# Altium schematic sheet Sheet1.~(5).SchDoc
size B; SheetNumber: 1; SheetTotal: 1
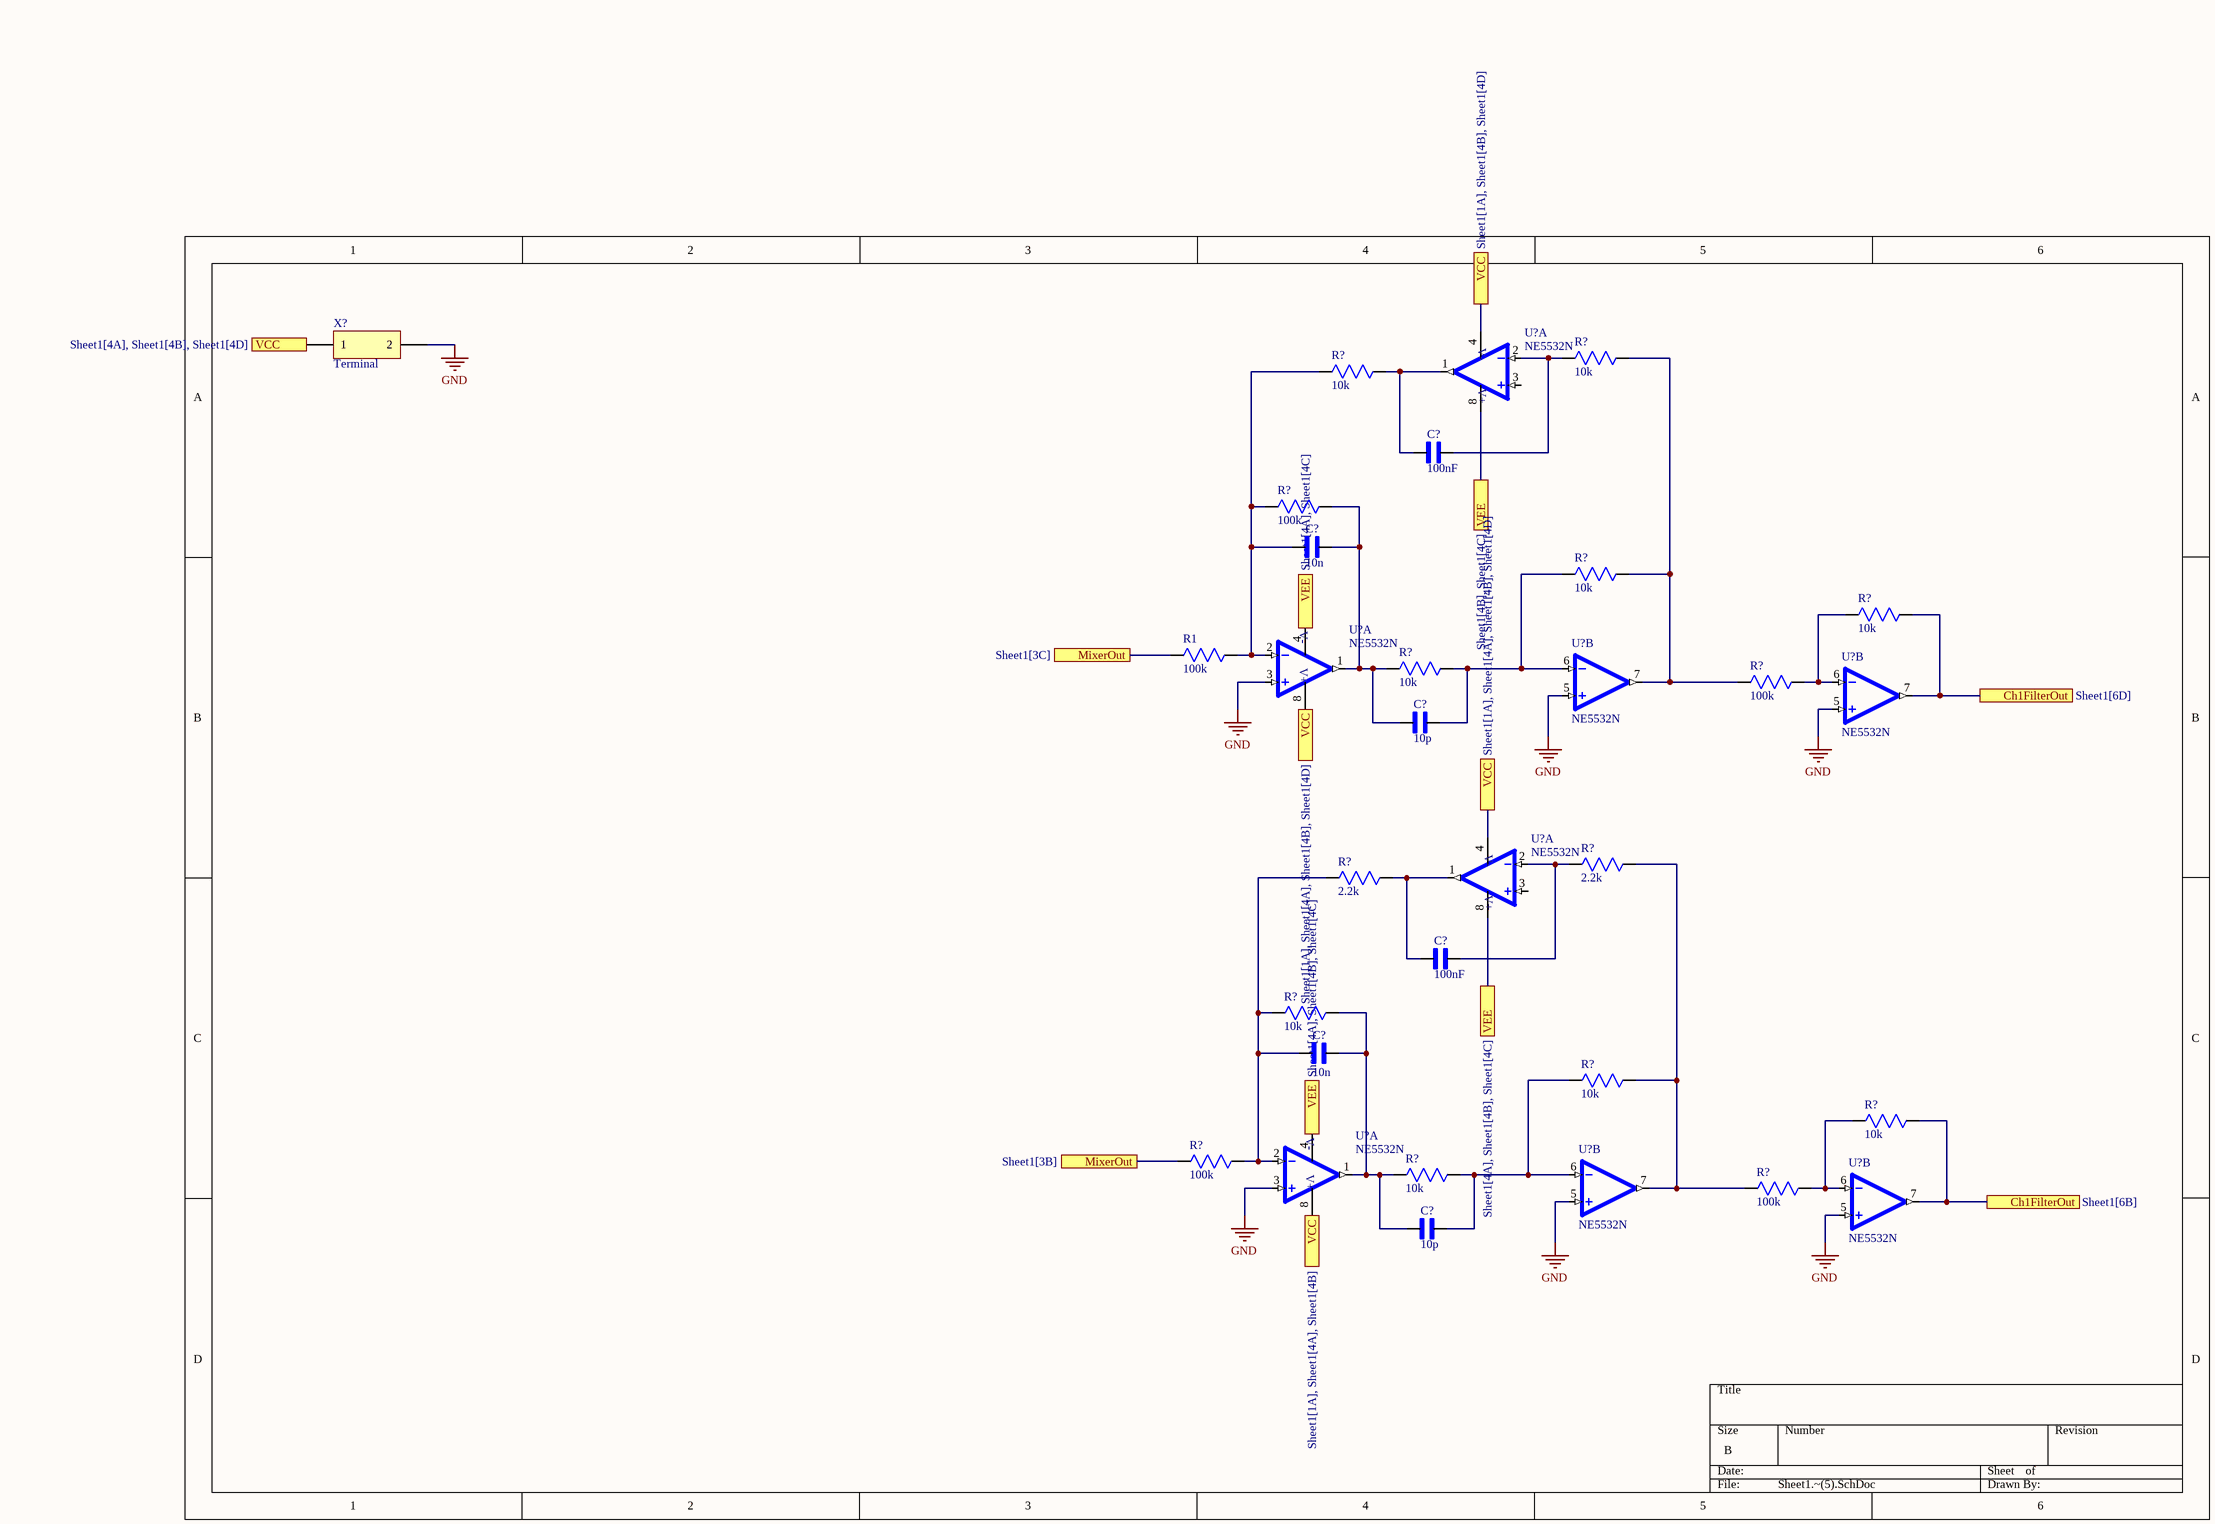
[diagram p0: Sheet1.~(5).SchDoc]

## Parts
(Parts that share a designator on the sheet are numbered #1, #2 ... from top to bottom, then left to right.)
C?#1  100nF  [CAPC2012X95N]
C?#2  10n  [CAPC2012X95N]
C?#3  10p  [CAPC2012X95N]
C?#4  100nF  [CAPC2012X95N]
C?#5  10n  [CAPC2012X95N]
C?#6  10p  [CAPC2012X95N]
R1  100k  [RC0805N_YAG-M]
R?#1  10k  [RC0805N_YAG-M]
R?#2  10k  [RC0805N_YAG-M]
R?#3  100k  [RC0805N_YAG-M]
R?#4  10k  [RC0805N_YAG-M]
R?#5  10k  [RC0805N_YAG-M]
R?#6  10k  [RC0805N_YAG-M]
R?#7  100k  [RC0805N_YAG-M]
R?#8  2.2k  [RC0805N_YAG-M]
R?#9  2.2k  [RC0805N_YAG-M]
R?#10  10k  [RC0805N_YAG-M]
R?#11  10k  [RC0805N_YAG-M]
R?#12  10k  [RC0805N_YAG-M]
R?#13  100k  [RC0805N_YAG-M]
R?#14  10k  [RC0805N_YAG-M]
R?#15  100k  [RC0805N_YAG-M]
U?#1  NE5532N  [DIP766W45P254L1016H533Q8]  (part A of 2)
U?#2  NE5532N  [DIP766W45P254L1016H533Q8]  (part A of 2)
U?#3  NE5532N  [DIP766W45P254L1016H533Q8]  (part B of 2)
U?#4  NE5532N  [DIP766W45P254L1016H533Q8]  (part B of 2)
U?#5  NE5532N  [DIP766W45P254L1016H533Q8]  (part A of 2)
U?#6  NE5532N  [DIP766W45P254L1016H533Q8]  (part A of 2)
U?#7  NE5532N  [DIP766W45P254L1016H533Q8]  (part B of 2)
U?#8  NE5532N  [DIP766W45P254L1016H533Q8]  (part B of 2)
X?  Terminal  [CON_TERMINAL_2POL]

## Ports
Ch1FilterOut (see Sheet1[6B]), Ch1FilterOut (see Sheet1[6D]), MixerOut (see Sheet1[3B]), MixerOut (see Sheet1[3C]), VCC (see Sheet1[1A], Sheet1[4A], Sheet1[4B]), VCC (see Sheet1[1A], Sheet1[4A], Sheet1[4B], Sheet1[4D]), VCC (see Sheet1[1A], Sheet1[4B], Sheet1[4D]), VCC (see Sheet1[4A], Sheet1[4B], Sheet1[4D]), VEE (see Sheet1[4A], Sheet1[4B], Sheet1[4C]), VEE (see Sheet1[4A], Sheet1[4C]), VEE (see Sheet1[4B], Sheet1[4C])

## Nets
GND: U?#2.3(+INA) U?#3.5(+INB) U?#4.5(+INB) U?#6.3(+INA) U?#7.5(+INB) U?#8.5(+INB) X?.2
Ch1FilterOut: R?#5.1 R?#12.1 U?#4.7(OUTB) U?#8.7(OUTB) ; port Ch1FilterOut
MixerOut: R1.2 R?#13.2 ; port MixerOut
VCC: U?#1.4(V-) U?#2.8(V+) U?#5.4(V-) U?#6.8(V+) X?.1 ; port VCC
VEE: U?#1.8(V+) U?#2.4(V-) U?#5.8(V+) U?#6.4(V-) ; port VEE
NetC?#1_1: C?#1.1 R?#2.1 U?#1.1(OUTA)
NetC?#1_2: C?#1.2 R?#1.2 U?#1.2(-INA)
NetC?#2_1: C?#2.1 R1.1 R?#2.2 R?#3.2 U?#2.2(-INA)
NetC?#2_2: C?#2.2 C?#3.1 R?#3.1 R?#6.2 U?#2.1(OUTA)
NetC?#3_2: C?#3.2 R?#4.2 R?#6.1 U?#3.6(-INB)
NetC?#4_1: C?#4.1 R?#9.1 U?#5.1(OUTA)
NetC?#4_2: C?#4.2 R?#8.2 U?#5.2(-INA)
NetC?#5_1: C?#5.1 R?#9.2 R?#10.2 R?#13.1 U?#6.2(-INA)
NetC?#5_2: C?#5.2 C?#6.1 R?#10.1 R?#14.2 U?#6.1(OUTA)
NetC?#6_2: C?#6.2 R?#11.2 R?#14.1 U?#7.6(-INB)
NetR?#1_1: R?#1.1 R?#4.1 R?#7.2 U?#3.7(OUTB)
NetR?#5_2: R?#5.2 R?#7.1 U?#4.6(-INB)
NetR?#8_1: R?#8.1 R?#11.1 R?#15.2 U?#7.7(OUTB)
NetR?#12_2: R?#12.2 R?#15.1 U?#8.6(-INB)

Not connected (* = marked no-connect by the designer): U?#1 3(+INA); U?#5 3(+INA)

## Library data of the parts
C?#1 C?#4 = CAP_0805_GENERIC: 0.1 ÂµF Â±10% 50V Ceramic Capacitor X7R 0805 (2012 Metric); MF: Samsung Electro-Mechanics; MP: CL21B104KBCNNNC
C?#2 C?#3 C?#5 C?#6 = CAP_0805_GENERIC: 0.1 ÂµF Â±10% 50V Ceramic Capacitor X7R 0805 (2012 Metric); Value: 100nF; MF: Samsung Electro-Mechanics; MP: CL21B104KBCNNNC
R1 R?#3 R?#7-R?#9 R?#13 R?#15 = RES_0805_GENERIC_1: Description; Manufacturer_Name: Yageo; Manufacturer_Part_Number: RC0805FR-0710KL; Value: 10k
R?#1 R?#2 R?#4-R?#6 R?#10-R?#12 R?#14 = RES_0805_GENERIC_1: Description; Manufacturer_Name: Yageo; Manufacturer_Part_Number: RC0805FR-0710KL
U?#1-U?#8 = NE5532N: IC, OP AMP, DUAL; No. of Amplifiers: 2 Amplifier; Bandwidth: 10MHz; Slew Rate: 8V/Âµs; Supply Voltage Range: Â± 15V; Amplifier Case Style: DIP; No. of Pins: 8Pins; Operating Temperature Min: 0Â°C; Operating Temperature Max: 70Â°C; MSL: -; SVHC: No SVHC (1; MF: Fairchild Semiconductor
X? = CON_TERMINAL_2POL: Terminal Screw; Manufacturer_Name: Yageo; Manufacturer_Part_Number: RC0805FR-0710KL; Value: 10k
